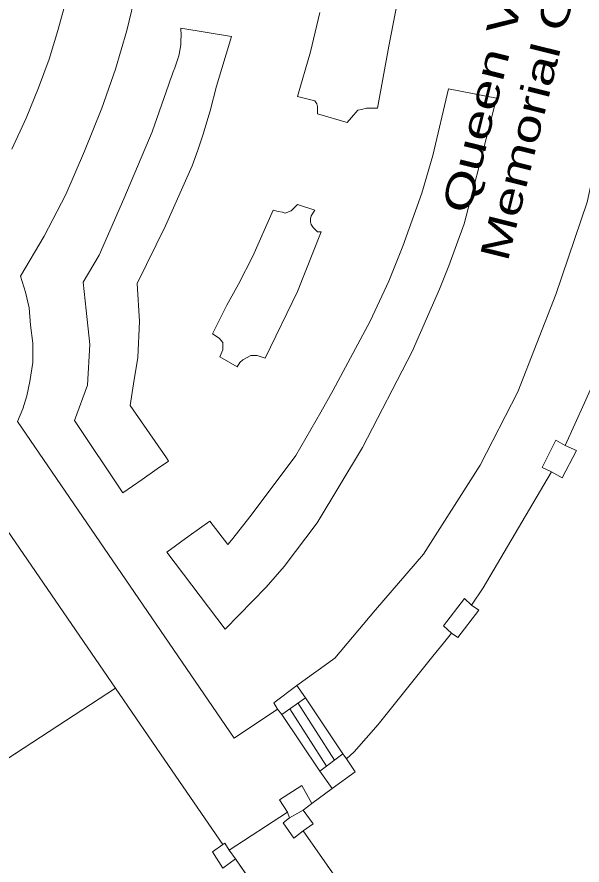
# Model space of a CAD drawing. Extents: x 528790 to 529292, y 179350 to 179856.
# Drawn here: x 529200.1 to 529239.4, y 179668.3 to 179727.2 of the extents above; entities that cross this region are included whole.
import ezdxf

# ---------------------------------------------------------------- set-up
doc = ezdxf.new("R2010")
doc.units = 0
doc.header["$LTSCALE"] = 0.6
doc.layers.add('1', color=7, linetype='Continuous', lineweight=13)
doc.layers.add('2', color=7, linetype='Continuous', lineweight=13)
doc.layers.add('5', color=7, linetype='Continuous')

msp = doc.modelspace()

# ---------------------------------------------------------------- linework, layer by layer
at = {"layer": '1'}
for points in [[(529199.75, 179718.05), (529200.75, 179720.2), (529201.6, 179722.3), (529202.35, 179724.3), (529202.95, 179726.3), (529203.5, 179728.3), (529203.9, 179730.3), (529204.25, 179733.5), (529204.29, 179733.98), (529185.48, 179736.56)], [(529195.25, 179697.6), (529206.95, 179680.56), (529210.637, 179675.185), (529214.4, 179669.7), (529214.55, 179669.8), (529214.85, 179669.3), (529218.9, 179671.95), (529218.35, 179672.8), (529219.9, 179673.8), (529220.6, 179672.55), (529222, 179673.6), (529221.15, 179674.8), (529218.5, 179678.75), (529218.2, 179679.1), (529215.2, 179677.1), (529200.15, 179699.1), (529200.5, 179700), (529200.8, 179700.9), (529201, 179701.9), (529201.2, 179703.2), (529201.2, 179704.55), (529201.05, 179705.8), (529200.95, 179707), (529200.7, 179708.1), (529200.35, 179709.2), (529202, 179712), (529203.5, 179714.9), (529204.8, 179717.9), (529206, 179720.9), (529206.95, 179723.6), (529207.75, 179726.3), (529208.4, 179729.1)], [(529208.4, 179729.1), (529207.75, 179726.3), (529206.95, 179723.6), (529206, 179720.9), (529204.8, 179717.9), (529203.5, 179714.9), (529202, 179712), (529200.35, 179709.2), (529200.7, 179708.1), (529200.95, 179707), (529201.05, 179705.8), (529201.2, 179704.55), (529201.2, 179703.2), (529201, 179701.9), (529200.8, 179700.9), (529200.5, 179700), (529200.15, 179699.1), (529215.2, 179677.1), (529218.2, 179679.1), (529217.95, 179679.55), (529219.55, 179680.75), (529222.196, 179682.662), (529225.03, 179686.006), (529228.36, 179689.891), (529232.289, 179696.08), (529234.915, 179701.167), (529237.56, 179707.947), (529239.742, 179714.36)], [(529226.7, 179729.05), (529225.95, 179725.2), (529225.15, 179720.9), (529224.4, 179720.9), (529224.05, 179720.8), (529223.8, 179720.75), (529223.35, 179720.25), (529223.05, 179719.9), (529221, 179720.5), (529221, 179721), (529220.95, 179721.2), (529220.8, 179721.4), (529220.25, 179721.55), (529219.6, 179721.7), (529220.5, 179724.8), (529221.15, 179727.55)], [(529221.15, 179727.55), (529220.5, 179724.8), (529219.6, 179721.7), (529220.25, 179721.55), (529220.8, 179721.4), (529220.95, 179721.2), (529221, 179721), (529221, 179720.5), (529223.05, 179719.9), (529223.35, 179720.25), (529223.8, 179720.75), (529224.05, 179720.8), (529224.4, 179720.9), (529225.15, 179720.9), (529225.95, 179725.2), (529226.7, 179729.05)], [(529203.5, 179728.3), (529202.95, 179726.3), (529202.35, 179724.3), (529201.6, 179722.3), (529200.75, 179720.2), (529199.75, 179718.05)], [(529239.742, 179714.36), (529237.56, 179707.947), (529234.915, 179701.167), (529232.289, 179696.08), (529228.36, 179689.891), (529225.03, 179686.006), (529222.196, 179682.662), (529219.55, 179680.75), (529220.15, 179679.9), (529222.75, 179676), (529223, 179675.65), (529223.55, 179676.15), (529225.2, 179678.05), (529229, 179682.8), (529229.75, 179683.7), (529230.3, 179684.4), (529229.75, 179684.9), (529231.2, 179686.8), (529231.7, 179686.35), (529232.5, 179687.55), (529235.2, 179692.1), (529237.25, 179695.6), (529236.6, 179695.9), (529237.55, 179697.8), (529238.2, 179697.45), (529239.55, 179700.4)], [(529239.55, 179700.4), (529238.2, 179697.45), (529239, 179697.1), (529238, 179695.2), (529237.25, 179695.6), (529235.2, 179692.1), (529232.5, 179687.55), (529231.7, 179686.35), (529232.2, 179686), (529230.75, 179684.1), (529230.3, 179684.4), (529229.75, 179683.7), (529229, 179682.8), (529225.2, 179678.05), (529223.55, 179676.15), (529223, 179675.65), (529223.6, 179674.75), (529222, 179673.6), (529220.6, 179672.55), (529220, 179672.1), (529220.7, 179671.15), (529220, 179670.65), (529225, 179663.5)], [(529190.23, 179669.65), (529206.95, 179680.56), (529195.25, 179697.6)], [(529231.963, 179644.552), (529215.3, 179668.7), (529214.4, 179668.05), (529213.7, 179669.2), (529214.4, 179669.7), (529210.637, 179675.185), (529206.95, 179680.56), (529190.23, 179669.65), (529190.5, 179669.4), (529191, 179668.8), (529193.969, 179664.512)], [(529225, 179663.5), (529220, 179670.65), (529219.35, 179670.15), (529218.6, 179671.2), (529219.05, 179671.55), (529218.9, 179671.95), (529214.85, 179669.3), (529215.3, 179668.7), (529231.963, 179644.552)]]:
    msp.add_lwpolyline(points, dxfattribs=at)
for points in [[(529208.209, 179701.731), (529207.972, 179700.224), (529210.493, 179696.573), (529210.639, 179696.362), (529209.851, 179695.811), (529208.807, 179695.08), (529207.462, 179694.139), (529204.094, 179699.187), (529205.012, 179701.64), (529205.175, 179704.462), (529204.903, 179706.842), (529204.697, 179708.784), (529205.809, 179710.675), (529207.529, 179714.577), (529209.494, 179719.234), (529210.655, 179722.567), (529210.754, 179722.848), (529210.86, 179723.128), (529210.968, 179723.407), (529211.075, 179723.685), (529211.178, 179723.965), (529211.271, 179724.247), (529211.352, 179724.532), (529211.448, 179725.019), (529211.482, 179725.315), (529211.503, 179725.612), (529211.512, 179725.91), (529211.498, 179726.461), (529215.014, 179725.866), (529213.979, 179722.409), (529213.538, 179720.701), (529213.028, 179719.012), (529212.662, 179717.976), (529212.273, 179716.876), (529210.43, 179712.722), (529208.46, 179708.692), (529208.609, 179706.06), (529208.506, 179703.552)], [(529208.807, 179695.08), (529209.851, 179695.811), (529210.639, 179696.362), (529210.493, 179696.573), (529207.972, 179700.224), (529208.209, 179701.731), (529208.506, 179703.552), (529208.609, 179706.06), (529208.46, 179708.692), (529210.43, 179712.722), (529212.273, 179716.876), (529212.662, 179717.976), (529213.028, 179719.012), (529213.538, 179720.701), (529213.979, 179722.409), (529215.014, 179725.866), (529211.498, 179726.461), (529211.512, 179725.91), (529211.503, 179725.612), (529211.482, 179725.315), (529211.448, 179725.019), (529211.352, 179724.532), (529211.271, 179724.247), (529211.178, 179723.965), (529211.075, 179723.685), (529210.968, 179723.407), (529210.86, 179723.128), (529210.754, 179722.848), (529210.655, 179722.567), (529209.494, 179719.234), (529207.529, 179714.577), (529205.809, 179710.675), (529204.697, 179708.784), (529204.903, 179706.842), (529205.175, 179704.462), (529205.012, 179701.64), (529204.094, 179699.187), (529207.462, 179694.139)], [(529230.092, 179722.24), (529233.421, 179721.58), (529232.331, 179717.307), (529231.18, 179712.846), (529230.122, 179709.937), (529229.465, 179708.317), (529227.56, 179703.974), (529224.11, 179697.297), (529220.959, 179692.066), (529218.665, 179689.03), (529217.426, 179687.583), (529214.568, 179684.673), (529210.508, 179690.028), (529212.075, 179691.159), (529213.498, 179692.187), (529214.766, 179690.568), (529215.004, 179690.866), (529216.378, 179692.589), (529219.475, 179696.754), (529221.226, 179699.753), (529222.068, 179701.291), (529224.658, 179706.079), (529225.937, 179708.868), (529226.93, 179711.303), (529228.23, 179714.989), (529229.005, 179717.591)], [(529220.959, 179692.066), (529224.11, 179697.297), (529227.56, 179703.974), (529229.465, 179708.317), (529230.122, 179709.937), (529231.18, 179712.846), (529232.331, 179717.307), (529233.421, 179721.58), (529230.092, 179722.24), (529229.005, 179717.591), (529228.23, 179714.989), (529226.93, 179711.303), (529225.937, 179708.868), (529224.658, 179706.079), (529222.068, 179701.291), (529221.226, 179699.753), (529219.475, 179696.754), (529216.378, 179692.589), (529215.004, 179690.866), (529214.766, 179690.568), (529213.498, 179692.187), (529212.075, 179691.159), (529210.508, 179690.028), (529214.568, 179684.673), (529217.426, 179687.583), (529218.665, 179689.03)], [(529219.6, 179714.2), (529220.8, 179713.8), (529220.55, 179713.4), (529220.5, 179713.2), (529220.5, 179713), (529220.55, 179712.8), (529220.7, 179712.6), (529221, 179712.3), (529221.25, 179712.3), (529219.6, 179708.15), (529217.35, 179703.5), (529216.8, 179703.7), (529216.35, 179703.7), (529215.8, 179703.4), (529215.6, 179703.2), (529215.4, 179702.9), (529214.2, 179703.6), (529214.4, 179704.1), (529214.4, 179704.6), (529214.15, 179704.9), (529213.7, 179705.2), (529214.7, 179707.2), (529215.5, 179708.65), (529216.5, 179710.6), (529217.9, 179713.8), (529218.25, 179713.7), (529218.55, 179713.65), (529218.75, 179713.6), (529219.15, 179713.75)], [(529217.9, 179713.8), (529216.5, 179710.6), (529215.5, 179708.65), (529214.7, 179707.2), (529213.7, 179705.2), (529214.15, 179704.9), (529214.4, 179704.6), (529214.4, 179704.1), (529214.2, 179703.6), (529215.4, 179702.9), (529215.6, 179703.2), (529215.8, 179703.4), (529216.35, 179703.7), (529216.8, 179703.7), (529217.35, 179703.5), (529219.6, 179708.15), (529221.25, 179712.3), (529221, 179712.3), (529220.7, 179712.6), (529220.55, 179712.8), (529220.5, 179713), (529220.5, 179713.2), (529220.55, 179713.4), (529220.8, 179713.8), (529219.6, 179714.2), (529219.15, 179713.75), (529218.75, 179713.6), (529218.55, 179713.65), (529218.25, 179713.7)], [(529238.2, 179697.45), (529237.55, 179697.8), (529236.6, 179695.9), (529237.25, 179695.6), (529238, 179695.2), (529239, 179697.1)], [(529231.7, 179686.35), (529231.2, 179686.8), (529229.75, 179684.9), (529230.3, 179684.4), (529230.75, 179684.1), (529232.2, 179686)], [(529218.5, 179678.75), (529220.15, 179679.9), (529219.55, 179680.75), (529217.95, 179679.55), (529218.2, 179679.1)], [(529222.75, 179676), (529220.15, 179679.9), (529218.5, 179678.75), (529221.15, 179674.8)], [(529221.15, 179674.8), (529222, 179673.6), (529223.6, 179674.75), (529223, 179675.65), (529222.75, 179676)], [(529220, 179672.1), (529220.6, 179672.55), (529219.9, 179673.8), (529218.35, 179672.8), (529218.9, 179671.95), (529219.05, 179671.55)], [(529219.05, 179671.55), (529218.6, 179671.2), (529219.35, 179670.15), (529220, 179670.65), (529220.7, 179671.15), (529220, 179672.1)], [(529214.4, 179669.7), (529213.7, 179669.2), (529214.4, 179668.05), (529215.3, 179668.7), (529214.85, 179669.3), (529214.55, 179669.8)]]:
    msp.add_lwpolyline(points, close=True, dxfattribs=at)
at = {"layer": '2'}
for p, q in [((529190.23, 179669.65), (529206.95, 179680.56)), ((529219.55, 179680.75), (529220.15, 179679.9)), ((529220.15, 179679.9), (529218.5, 179678.75)), ((529220.15, 179679.9), (529222.75, 179676)), ((529219.63, 179679.54), (529222.17, 179675.56)), ((529218.5, 179678.75), (529218.2, 179679.1)), ((529218.5, 179678.75), (529221.15, 179674.8)), ((529221.62, 179675.15), (529219.06, 179679.14)), ((529222.75, 179676), (529221.15, 179674.8)), ((529223, 179675.65), (529222.75, 179676)), ((529221.15, 179674.8), (529222, 179673.6)), ((529220.6, 179672.55), (529222, 179673.6)), ((529220.6, 179672.55), (529220, 179672.1)), ((529214.85, 179669.3), (529218.9, 179671.95)), ((529219.05, 179671.55), (529218.9, 179671.95)), ((529220, 179672.1), (529219.05, 179671.55)), ((529225, 179663.5), (529220, 179670.65)), ((529214.85, 179669.3), (529215.3, 179668.7)), ((529231.963, 179644.552), (529215.3, 179668.7))]:
    msp.add_line(p, q, dxfattribs=at)
for points in [[(529236.4, 179771.25), (529238.027, 179768.771), (529239.792, 179763.192), (529241.537, 179756.249), (529242.522, 179750.938), (529243.267, 179743.777), (529243.256, 179737.939), (529242.882, 179730.404), (529241.36, 179721.821), (529239.742, 179714.36), (529237.56, 179707.947), (529234.915, 179701.167), (529232.289, 179696.08), (529228.36, 179689.891), (529225.03, 179686.006), (529222.196, 179682.662), (529219.55, 179680.75)], [(529199.75, 179718.05), (529200.75, 179720.2), (529201.6, 179722.3), (529202.35, 179724.3), (529202.95, 179726.3), (529203.5, 179728.3), (529203.9, 179730.3), (529204.25, 179733.5), (529204.29, 179733.98)], [(529208.4, 179729.1), (529207.75, 179726.3), (529206.95, 179723.6), (529206, 179720.9), (529204.8, 179717.9), (529203.5, 179714.9), (529202, 179712), (529200.35, 179709.2), (529200.7, 179708.1), (529200.95, 179707), (529201.05, 179705.8), (529201.2, 179704.55), (529201.2, 179703.2), (529201, 179701.9), (529200.8, 179700.9), (529200.5, 179700), (529200.15, 179699.1), (529215.2, 179677.1), (529218.2, 179679.1)], [(529221.15, 179727.55), (529220.5, 179724.8), (529219.6, 179721.7), (529220.25, 179721.55), (529220.8, 179721.4), (529220.95, 179721.2), (529221, 179721), (529221, 179720.5), (529223.05, 179719.9), (529223.35, 179720.25), (529223.8, 179720.75), (529224.05, 179720.8), (529224.4, 179720.9), (529225.15, 179720.9), (529225.95, 179725.2), (529226.7, 179729.05)], [(529238.2, 179697.45), (529239.55, 179700.4), (529242.65, 179707.35)], [(529206.95, 179680.56), (529195.25, 179697.6)], [(529237.25, 179695.6), (529236.6, 179695.9), (529237.55, 179697.8), (529238.2, 179697.45)], [(529238.2, 179697.45), (529239, 179697.1), (529238, 179695.2), (529237.25, 179695.6)], [(529231.7, 179686.35), (529232.5, 179687.55), (529235.2, 179692.1), (529237.25, 179695.6)], [(529231.7, 179686.35), (529231.2, 179686.8), (529229.75, 179684.9), (529230.3, 179684.4)], [(529231.7, 179686.35), (529232.2, 179686), (529230.75, 179684.1), (529230.3, 179684.4)], [(529223, 179675.65), (529223.55, 179676.15), (529225.2, 179678.05), (529229, 179682.8), (529229.75, 179683.7), (529230.3, 179684.4)], [(529214.4, 179669.7), (529210.637, 179675.185), (529206.95, 179680.56)], [(529218.2, 179679.1), (529217.95, 179679.55), (529219.55, 179680.75)], [(529222, 179673.6), (529223.6, 179674.75), (529223, 179675.65)], [(529218.9, 179671.95), (529218.35, 179672.8), (529219.9, 179673.8), (529220.6, 179672.55)], [(529220, 179672.1), (529220.7, 179671.15), (529220, 179670.65)], [(529220, 179670.65), (529219.35, 179670.15), (529218.6, 179671.2), (529219.05, 179671.55)], [(529215.3, 179668.7), (529214.4, 179668.05), (529213.7, 179669.2), (529214.4, 179669.7)], [(529214.4, 179669.7), (529214.55, 179669.8), (529214.85, 179669.3)]]:
    msp.add_lwpolyline(points, dxfattribs=at)
for points in [[(529210.639, 179696.362), (529209.851, 179695.811), (529208.807, 179695.08), (529207.462, 179694.139), (529204.094, 179699.187), (529205.012, 179701.64), (529205.175, 179704.462), (529204.903, 179706.842), (529204.697, 179708.784), (529205.809, 179710.675), (529207.529, 179714.577), (529209.494, 179719.234), (529210.655, 179722.567), (529210.754, 179722.848), (529210.86, 179723.128), (529210.968, 179723.407), (529211.075, 179723.685), (529211.178, 179723.965), (529211.271, 179724.247), (529211.352, 179724.532), (529211.448, 179725.019), (529211.482, 179725.315), (529211.503, 179725.612), (529211.512, 179725.91), (529211.498, 179726.461), (529215.014, 179725.866), (529213.979, 179722.409), (529213.538, 179720.701), (529213.028, 179719.012), (529212.662, 179717.976), (529212.273, 179716.876), (529210.43, 179712.722), (529208.46, 179708.692), (529208.609, 179706.06), (529208.506, 179703.552), (529208.209, 179701.731), (529207.972, 179700.224), (529210.493, 179696.573)], [(529213.498, 179692.187), (529212.075, 179691.159), (529210.508, 179690.028), (529214.568, 179684.673), (529217.426, 179687.583), (529218.665, 179689.03), (529220.959, 179692.066), (529224.11, 179697.297), (529227.56, 179703.974), (529229.465, 179708.317), (529230.122, 179709.937), (529231.18, 179712.846), (529232.331, 179717.307), (529233.421, 179721.58), (529230.092, 179722.24), (529229.005, 179717.591), (529228.23, 179714.989), (529226.93, 179711.303), (529225.937, 179708.868), (529224.658, 179706.079), (529222.068, 179701.291), (529221.226, 179699.753), (529219.475, 179696.754), (529216.378, 179692.589), (529215.004, 179690.866), (529214.766, 179690.568)], [(529217.9, 179713.8), (529216.5, 179710.6), (529215.5, 179708.65), (529214.7, 179707.2), (529213.7, 179705.2), (529214.15, 179704.9), (529214.4, 179704.6), (529214.4, 179704.1), (529214.2, 179703.6), (529215.4, 179702.9), (529215.6, 179703.2), (529215.8, 179703.4), (529216.35, 179703.7), (529216.8, 179703.7), (529217.35, 179703.5), (529219.6, 179708.15), (529221.25, 179712.3), (529221, 179712.3), (529220.7, 179712.6), (529220.55, 179712.8), (529220.5, 179713), (529220.5, 179713.2), (529220.55, 179713.4), (529220.8, 179713.8), (529219.6, 179714.2), (529219.15, 179713.75), (529218.75, 179713.6), (529218.55, 179713.65), (529218.25, 179713.7)]]:
    msp.add_lwpolyline(points, close=True, dxfattribs=at)

# ---------------------------------------------------------------- texts
at = {"layer": '5'}
for s, width, p in [('Memorial Gardens', 1.4, (529234.2, 179710.15)), ('Queen Victoria', 1.45, (529231.55, 179713.45))]:
    msp.add_text(s, height=2, rotation=76, dxfattribs=dict(at, width=width)).set_placement(p)

doc.saveas('drawing.dxf')
